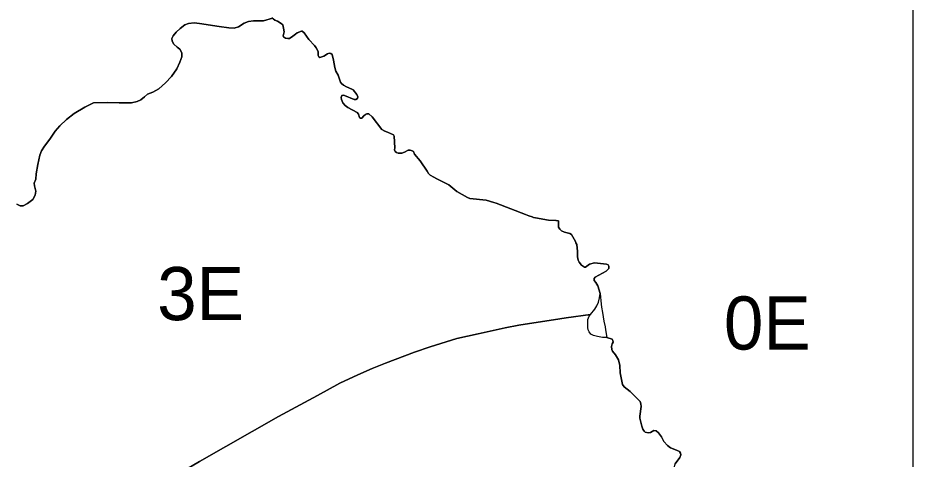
# Model space of a CAD drawing. Extents: x 152750 to 166250, y 378996 to 390000.
# Drawn here: x 162877 to 166250, y 384626 to 386288 of the extents above; entities that cross this region are included whole.
import ezdxf

# ---------------------------------------------------------------- set-up
doc = ezdxf.new("R2010")
doc.units = 0
doc.layers.add('BLT_Nummers', color=7, linetype='Continuous')
doc.layers.add('BLT_Shapes', color=7, linetype='Continuous')

msp = doc.modelspace()

# ---------------------------------------------------------------- linework, layer by layer
at = {"layer": 'BLT_Shapes'}
for p, q in [((163802.4, 386277.6), (163835.9, 386286.7)), ((163838.2, 386284.4), (163835.9, 386286.7)), ((163488.2, 386248.7), (163505.6, 386262.3)), ((163708.4, 386254.7), (163729.7, 386268.4)), ((163729.7, 386268.4), (163745.7, 386274.9)), ((163473.1, 386234.5), (163488.2, 386248.7)), ((163878, 386216.2), (163876.4, 386219.9)), ((163922.9, 386227.4), (163913.1, 386219.3)), ((163929.5, 386232), (163922.9, 386227.4)), ((163457.6, 386200.3), (163456.7, 386210.3)), ((164000, 386175.9), (163993.9, 386184.1)), ((163486.5, 386169.7), (163476.6, 386177.9)), ((164056.4, 386154), (164049.6, 386154.7)), ((164060.3, 386150.3), (164056.4, 386154)), ((164029.9, 386144.1), (164015, 386138.4)), ((164075.3, 386087.6), (164070.9, 386100.8)), ((164083.5, 386071.9), (164075.3, 386087.6)), ((164092.7, 386046.2), (164083.5, 386071.9)), ((163408.3, 386021.4), (163433.4, 386043.5)), ((164095.8, 386040.8), (164092.7, 386046.2)), ((164104, 386034.3), (164095.8, 386040.8)), ((164115, 386028.5), (164104, 386034.3)), ((164135.5, 386020.2), (164115, 386028.5)), ((164097.5, 385995.2), (164102.5, 385997.2)), ((164144.4, 385980.4), (164150.3, 385980.1)), ((164167.4, 385909.9), (164163.6, 385912.6)), ((164179.6, 385919.8), (164172.1, 385910.2)), ((164172.1, 385910.2), (164167.4, 385909.9)), ((164295, 385843.2), (164292.1, 385847.9)), ((162966, 385787.7), (162977.3, 385804.5)), ((164371.4, 385774.6), (164366.9, 385784.3)), ((162896.9, 385580.7), (162912.5, 385588.9)), ((162912.5, 385588.9), (162932.3, 385604.5)), ((164789.4, 385547.7), (164679.2, 385589.7)), ((164801.9, 385542.9), (164789.4, 385547.7)), ((165094.7, 385360.7), (165049.2, 385365.6)), ((165100.4, 385357.9), (165094.7, 385360.7)), ((165052.4, 385311.7), (165093.6, 385334)), ((165055, 385291.5), (165047.9, 385299)), ((165034.1, 385170.8), (165050.5, 385190.8)), ((164611.1, 385098.7), (164713.3, 385120.8)), ((165115.5, 385077.4), (165096.3, 385084.2)), ((165119, 385072.9), (165115.5, 385077.4)), ((165145.7, 384950.7), (165144.7, 384978.2)), ((165183.8, 384880.6), (165161.7, 384898)), ((165290.1, 384725.8), (165282.3, 384732.5)), ((165259.9, 384726.6), (165252.2, 384725.6)), ((165370, 384654.5), (165358.1, 384659.9)), ((165373.7, 384649.2), (165370, 384654.5)), ((165370.7, 384632.6), (165374.5, 384642.8)), ((165374.5, 384642.8), (165373.7, 384649.2))]:
    msp.add_line(p, q, dxfattribs=at)
for points in [[(166250, 382867.2), (166250, 386812.5)], [(163835.9, 386286.7), (163802.4, 386277.6), (163764.6, 386277.6), (163745.7, 386274.9), (163729.7, 386268.4), (163708.4, 386254.7)], [(163833.1, 386289.3), (163835.7, 386286.9), (163838.2, 386284.4), (163845.2, 386279.7), (163855.1, 386275.5), (163869.2, 386267.1), (163874.7, 386261.7), (163878, 386250), (163879.6, 386235), (163876.4, 386219.9), (163878, 386216.2), (163884.6, 386212), (163894.4, 386210.3), (163899.6, 386211), (163913.1, 386219.3), (163922.9, 386227.4), (163929.5, 386232), (163945.8, 386238.6), (163948, 386238.5), (163955, 386232.4), (163973, 386206.6), (163993.9, 386184.1), (164000, 386175.9), (164007.5, 386162.1), (164007.8, 386147), (164010.7, 386140.8), (164015, 386138.4), (164029.9, 386144.1), (164042.9, 386153.3), (164049.6, 386154.7), (164056.4, 386154), (164060.3, 386150.3), (164066.4, 386129), (164070.9, 386100.8), (164075.3, 386087.6), (164083.5, 386071.9), (164092.7, 386046.2), (164095.8, 386040.8), (164104, 386034.3), (164115, 386028.5), (164135.5, 386020.2), (164140.3, 386016.8), (164154.4, 386000), (164158.1, 385990.9), (164156.8, 385984.4), (164150.3, 385980.1), (164144.4, 385980.4), (164107.7, 385996.1), (164102.5, 385997.2), (164097.5, 385995.2), (164095.2, 385988.1), (164095.7, 385980.1), (164101.1, 385968.7), (164109.4, 385958.3), (164119.9, 385950.3), (164155.5, 385932.2), (164160.6, 385925.5), (164163.6, 385912.6), (164167.4, 385909.9), (164172.1, 385910.2), (164179.6, 385919.8), (164186.1, 385923.9), (164192.1, 385926.6), (164198.6, 385926.1), (164211.9, 385914.8), (164248.5, 385867.2), (164259.9, 385861.7), (164269.5, 385857.7), (164292.1, 385847.9), (164295, 385843.2), (164296.9, 385798.1), (164295.8, 385791.5), (164297.9, 385785.2), (164302.7, 385780.5), (164309.1, 385778.5), (164322.8, 385779), (164333.6, 385782.6), (164346.8, 385789.5), (164355.1, 385789.9), (164362.9, 385787.2), (164366.9, 385784.3), (164371.4, 385774.6), (164392.4, 385750), (164418.5, 385710.5), (164423.9, 385702), (164430.1, 385695.3), (164444.4, 385687.9), (164455.6, 385682.1), (164500, 385658.9), (164531, 385634.7), (164571.1, 385611.3), (164580.1, 385608.4), (164641.7, 385601.8), (164669.7, 385592.9), (164679.2, 385589.7), (164789.4, 385547.7), (164801.9, 385542.9), (164814, 385538.3), (164820.1, 385536), (164827.2, 385534.8), (164876.3, 385526.2), (164903.6, 385524.6), (164904.7, 385524.5), (164913.4, 385523.5), (164914, 385500), (164918.6, 385491.9), (164925.6, 385485.9), (164936.8, 385480.5), (164956.9, 385475.6), (164962.9, 385471.8), (164977.3, 385445.8), (164979.6, 385440.4), (164982.3, 385434), (164985.5, 385408.7), (164985.5, 385388.1), (164987.8, 385375.8), (164991.3, 385367.5), (165000, 385356.1), (165011.2, 385349.5), (165015.9, 385349.7), (165030.1, 385360.5), (165049.2, 385365.6), (165094.7, 385360.7), (165100.4, 385357.9), (165103.9, 385352.8), (165102.9, 385344.6), (165093.6, 385334), (165052.4, 385311.7), (165048.6, 385306.4), (165047.9, 385299), (165055, 385291.5), (165062.2, 385278.6), (165070.2, 385250), (165074.9, 385209.6), (165076.2, 385198.5), (165079.6, 385178.8), (165085.2, 385146), (165089, 385123.9), (165091, 385113), (165096.3, 385084.2), (165115.5, 385077.4), (165119, 385072.9), (165119.6, 385067.1), (165116.1, 385061), (165113.9, 385050.1), (165114.9, 385039.2), (165117, 385033), (165129.1, 385019.1), (165140.3, 385000), (165144.7, 384978.2), (165145.7, 384950.7), (165154.7, 384906.7), (165161.7, 384898), (165183.8, 384880.6), (165191.7, 384873.7), (165221.6, 384843), (165224.4, 384835), (165225, 384824.8), (165220.2, 384788.5), (165220.5, 384780.9), (165227.5, 384750), (165231.3, 384738.9), (165236.2, 384731.3), (165240.7, 384728.1), (165252.2, 384725.6), (165259.9, 384726.6), (165272.9, 384733.8), (165282.3, 384732.5), (165290.1, 384725.8), (165301.9, 384709.9), (165306.1, 384702), (165311.1, 384692), (165324.2, 384677.5), (165336, 384669.2), (165358.1, 384659.9), (165370, 384654.5), (165373.7, 384649.2), (165374.5, 384642.8), (165370.7, 384632.6), (165353.9, 384608.6)], [(163835.9, 386286.7), (163835.7, 386286.9), (163833.1, 386289.3)], [(163869.2, 386267.1), (163855.1, 386275.5), (163845.2, 386279.7), (163838.2, 386284.4)], [(163708.4, 386254.7), (163692.2, 386249.3), (163672.1, 386250.8), (163635.1, 386256.2), (163560.9, 386267.1), (163540.3, 386269.4), (163519.9, 386266.9), (163505.6, 386262.3), (163488.2, 386248.7), (163473.1, 386234.5), (163461.9, 386220.2), (163456.7, 386210.3), (163457.6, 386200.3), (163464, 386189.1), (163476.6, 386177.9), (163486.5, 386169.7), (163493.8, 386156.3), (163494.3, 386141.6), (163486.9, 386121.3), (163475.3, 386096.6), (163455.8, 386067.2), (163433.4, 386043.5), (163408.3, 386021.4), (163384.6, 386008.5), (163365.1, 386000.3), (163354.3, 385990.8), (163339.6, 385979.1), (163325.8, 385973.5), (163304.2, 385968.7), (163258.4, 385968.7), (163214.4, 385969.2), (163161.7, 385968.3), (163129.3, 385951.9), (163089.1, 385928.1), (163060.2, 385904.8), (163034.7, 385881.9), (163017.4, 385861.6), (162997.1, 385830.9), (162977.3, 385804.5), (162966, 385787.7), (162959.6, 385770.8), (162951.8, 385735.4), (162945.3, 385700.4), (162943.6, 385680.5), (162938.4, 385665), (162939.7, 385655), (162944, 385635.6), (162941.4, 385620.9), (162932.3, 385604.5), (162912.5, 385588.9), (162896.9, 385580.7), (162885.7, 385580.3), (162872.7, 385586.3)], [(163505.6, 386262.3), (163519.9, 386266.9), (163540.3, 386269.4), (163560.9, 386267.1), (163635.1, 386256.2)], [(163635.1, 386256.2), (163672.1, 386250.8), (163692.2, 386249.3), (163708.4, 386254.7)], [(163745.7, 386274.9), (163764.6, 386277.6), (163802.4, 386277.6)], [(163878, 386250), (163874.7, 386261.7), (163869.2, 386267.1)], [(163876.4, 386219.9), (163879.6, 386235), (163878, 386250)], [(163456.7, 386210.3), (163461.9, 386220.2), (163473.1, 386234.5)], [(163894.4, 386210.3), (163884.6, 386212), (163878, 386216.2)], [(163913.1, 386219.3), (163899.6, 386211), (163894.4, 386210.3)], [(163993.9, 386184.1), (163973, 386206.6), (163955, 386232.4), (163948, 386238.5), (163945.8, 386238.6), (163929.5, 386232)], [(163476.6, 386177.9), (163464, 386189.1), (163457.6, 386200.3)], [(163494.3, 386141.6), (163493.8, 386156.3), (163486.5, 386169.7)], [(164015, 386138.4), (164010.7, 386140.8), (164007.8, 386147), (164007.5, 386162.1), (164000, 386175.9)], [(164049.6, 386154.7), (164042.9, 386153.3), (164029.9, 386144.1)], [(164070.9, 386100.8), (164066.4, 386129), (164060.3, 386150.3)], [(163475.3, 386096.6), (163486.9, 386121.3), (163494.3, 386141.6)], [(163433.4, 386043.5), (163455.8, 386067.2), (163475.3, 386096.6)], [(163325.8, 385973.5), (163339.6, 385979.1), (163354.3, 385990.8), (163365.1, 386000.3), (163384.6, 386008.5), (163408.3, 386021.4)], [(164150.3, 385980.1), (164156.8, 385984.4), (164158.1, 385990.9), (164154.4, 386000), (164140.3, 386016.8), (164135.5, 386020.2)], [(164119.9, 385950.3), (164109.4, 385958.3), (164101.1, 385968.7), (164095.7, 385980.1), (164095.2, 385988.1), (164097.5, 385995.2)], [(164102.5, 385997.2), (164107.7, 385996.1), (164144.4, 385980.4)], [(162977.3, 385804.5), (162997.1, 385830.9), (163017.4, 385861.6), (163034.7, 385881.9), (163060.2, 385904.8), (163089.1, 385928.1), (163129.3, 385951.9), (163161.7, 385968.3)], [(163161.7, 385968.3), (163214.4, 385969.2), (163258.4, 385968.7)], [(163258.4, 385968.7), (163304.2, 385968.7), (163325.8, 385973.5)], [(164163.6, 385912.6), (164160.6, 385925.5), (164155.5, 385932.2), (164119.9, 385950.3)], [(164198.6, 385926.1), (164192.1, 385926.6), (164186.1, 385923.9), (164179.6, 385919.8)], [(164248.5, 385867.2), (164211.9, 385914.8), (164198.6, 385926.1)], [(164292.1, 385847.9), (164269.5, 385857.7), (164259.9, 385861.7), (164248.5, 385867.2)], [(164297.9, 385785.2), (164295.8, 385791.5), (164296.9, 385798.1), (164295, 385843.2)], [(162951.8, 385735.4), (162959.6, 385770.8), (162966, 385787.7)], [(164309.1, 385778.5), (164302.7, 385780.5), (164297.9, 385785.2)], [(164346.8, 385789.5), (164333.6, 385782.6), (164322.8, 385779), (164309.1, 385778.5)], [(164366.9, 385784.3), (164362.9, 385787.2), (164355.1, 385789.9), (164346.8, 385789.5)], [(164500, 385658.9), (164455.6, 385682.1), (164444.4, 385687.9), (164430.1, 385695.3), (164423.9, 385702), (164418.5, 385710.5), (164392.4, 385750), (164371.4, 385774.6)], [(162943.6, 385680.5), (162945.3, 385700.4), (162951.8, 385735.4)], [(162944, 385635.6), (162939.7, 385655), (162938.4, 385665), (162943.6, 385680.5)], [(164571.1, 385611.3), (164531, 385634.7), (164500, 385658.9)], [(162932.3, 385604.5), (162941.4, 385620.9), (162944, 385635.6)], [(164641.7, 385601.8), (164580.1, 385608.4), (164571.1, 385611.3)], [(162872.7, 385586.3), (162885.7, 385580.3), (162896.9, 385580.7)], [(164679.2, 385589.7), (164669.7, 385592.9), (164641.7, 385601.8)], [(164827.2, 385534.8), (164820.1, 385536), (164814, 385538.3), (164801.9, 385542.9)], [(164904.7, 385524.5), (164903.6, 385524.6), (164876.3, 385526.2), (164827.2, 385534.8)], [(164914, 385500), (164913.4, 385523.5), (164904.7, 385524.5)], [(164925.6, 385485.9), (164918.6, 385491.9), (164914, 385500)], [(164977.3, 385445.8), (164962.9, 385471.8), (164956.9, 385475.6), (164936.8, 385480.5), (164925.6, 385485.9)], [(164982.3, 385434), (164979.6, 385440.4), (164977.3, 385445.8)], [(164985.5, 385388.1), (164985.5, 385408.7), (164982.3, 385434)], [(165011.2, 385349.5), (165000, 385356.1), (164991.3, 385367.5), (164987.8, 385375.8), (164985.5, 385388.1)], [(165049.2, 385365.6), (165030.1, 385360.5), (165015.9, 385349.7), (165011.2, 385349.5)], [(165093.6, 385334), (165102.9, 385344.6), (165103.9, 385352.8), (165100.4, 385357.9)], [(165047.9, 385299), (165048.6, 385306.4), (165052.4, 385311.7)], [(165070.2, 385250), (165062.2, 385278.6), (165055, 385291.5)], [(165050.5, 385190.8), (165057.9, 385203.4), (165064, 385217.3), (165068.6, 385233.1), (165070.2, 385250)], [(165034.1, 385170.8), (164943.2, 385157.8), (164918.8, 385154.9), (164764.2, 385130.5), (164713.3, 385120.8), (164611.1, 385098.7), (164530.5, 385081), (164429.9, 385049.5), (164371.3, 385029.6), (164261.9, 384987.6), (164212.2, 384967.1), (164157.5, 384943.4), (164090.1, 384911.9), (164005, 384866), (163859.2, 384786.4), (163561.4, 384617.8), (163469.7, 384563.7), (163317.7, 384476.3), (163247.4, 384435), (163117.5, 384358.5), (163090.9, 384342.8), (162880.5, 384225.3)], [(164713.3, 385120.8), (164764.2, 385130.5), (164918.8, 385154.9), (164943.2, 385157.8), (165034.1, 385170.8)], [(165096.3, 385084.2), (165079.4, 385084.9), (165060.6, 385088), (165045.6, 385091.9), (165035.5, 385097.3), (165029.3, 385105.7), (165026.1, 385113.2), (165024.6, 385122.3), (165024.2, 385136.2), (165024, 385145.5), (165024.8, 385152.5), (165026.6, 385158.7), (165029.4, 385164.4), (165034.1, 385170.8)], [(164371.3, 385029.6), (164429.9, 385049.5), (164530.5, 385081), (164611.1, 385098.7)], [(165114.9, 385039.2), (165113.9, 385050.1), (165116.1, 385061), (165119.6, 385067.1), (165119, 385072.9)], [(165129.1, 385019.1), (165117, 385033), (165114.9, 385039.2)], [(164157.5, 384943.4), (164212.2, 384967.1), (164261.9, 384987.6), (164371.3, 385029.6)], [(165144.7, 384978.2), (165140.3, 385000), (165129.1, 385019.1)], [(163247.4, 384435), (163317.7, 384476.3), (163469.7, 384563.7), (163561.4, 384617.8), (163859.2, 384786.4), (164005, 384866), (164090.1, 384911.9), (164157.5, 384943.4)], [(165161.7, 384898), (165154.7, 384906.7), (165145.7, 384950.7)], [(165224.4, 384835), (165221.6, 384843), (165191.7, 384873.7), (165183.8, 384880.6)], [(165227.5, 384750), (165220.5, 384780.9), (165220.2, 384788.5), (165225, 384824.8), (165224.4, 384835)], [(165236.2, 384731.3), (165231.3, 384738.9), (165227.5, 384750)], [(165282.3, 384732.5), (165272.9, 384733.8), (165259.9, 384726.6)], [(165252.2, 384725.6), (165240.7, 384728.1), (165236.2, 384731.3)], [(165358.1, 384659.9), (165336, 384669.2), (165324.2, 384677.5), (165311.1, 384692), (165306.1, 384702), (165301.9, 384709.9), (165290.1, 384725.8)], [(165350.4, 384596.6), (165353.9, 384608.6), (165370.7, 384632.6)]]:
    msp.add_lwpolyline(points, dxfattribs=at)

# ---------------------------------------------------------------- texts
at = {"layer": 'BLT_Nummers'}
for s, p in [('3E', (163401.5, 385149.6)), ('0E', (165537, 385039))]:
    msp.add_text(s, height=200, dxfattribs=at).set_placement(p)

doc.saveas('drawing.dxf')
